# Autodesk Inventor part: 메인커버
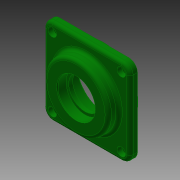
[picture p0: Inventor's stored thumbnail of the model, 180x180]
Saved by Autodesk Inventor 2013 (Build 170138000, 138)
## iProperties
Created: 2018-09
Part Number: 메인커버
Material: 알루미늄 6061
Document SubType Name: Modeling
Designer: mduedu
Density: 2.71 g/cm^3
Mass: 178.493 g
Surface Area: 197.445 cm^2
Volume: 65.8646 cm^3
Author: mduedu
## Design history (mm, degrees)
sketch "스케치1"
  geometry: L1 (-40, -40)-(40, -40); L2 (40, -40)-(40, 40); L3 (40, 40)-(-40, 40); L4 (-40, 40)-(-40, -40); L5 (-40, -40)-(40, 40); L6 (40, -40)-(-40, 40); 1 further point
  constraints: 12 end point, 2 midpoint, 2 parallel, 1 horizontal, 1 perpendicular
  dimensions: "d0" = 80 distance of L3.end L2.end; "d1" = 80 distance of L2.end L1.end
extrude "돌출1" new body sketch "스케치1" distance "d2" = 7; taper "d3" = 0 deg
sketch "스케치2"
  geometry: C1 r 30 at (0, 0); 1 further point
  constraints: 1 centre point, 1 coincident
  dimensions: "d4" = 60 diameter of C1
extrude "돌출2" join sketch "스케치2" distance "d5" = 10; taper "d6" = 0 deg
sketch "스케치3"
  geometry: C1 r 32.5 at (0, 0); 1 further point
  constraints: 1 centre point, 1 coincident
  dimensions: "d7" = 65 diameter of C1
extrude "돌출3" join sketch "스케치3" distance "d8" = 9; taper "d9" = 0 deg
sketch "스케치4"
  geometry: L1 (-32.5, -9)-(32.5, -9) reference; L2 (30, 17)-(-30, 17) reference; L3 (0, 17)-(0, -9); L4 (0, -9)-(23.5, -9); L5 (23.5, -9)-(23.5, 5); L6 (23.5, 5)-(0, 5); L7 (0, 5)-(0, -9); L8 (0, 5)-(15, 5); L9 (15, 5)-(15, 8.7); L10 (15, 8.7)-(0, 8.7); L11 (0, 8.7)-(0, 5); L12 (0, 8.7)-(17.5, 8.7); L13 (17.5, 8.7)-(17.5, 17); L14 (17.5, 17)-(0, 17); L15 (0, 17)-(0, 8.7); 1 further point
  constraints: 26 end point, 6 parallel, 3 horizontal, 3 perpendicular, 2 midpoint, 1 point on line
  dimensions: "d10" = 14 distance of L4.end L5.end; "d12" = 8.3 distance of L12.end L13.end; "d13" = 35 diameter of L13 L3; "d14" = 30 diameter of L9 L3; "d15" = 47 diameter of L5 L3
revolve "회전1" sketch "스케치4" stored, may be unused: angle "d16" = 90 deg
fillet "모깎기1" dims "d17" = 8
fillet "모깎기2" dims "d18" = 3
fillet "모깎기3" dims "d19" = 3
chamfer "모따기1" distance "d20" = 0.8; stored, may be unused: second distance "d21" = 2, angle "d22" = 30 deg
chamfer "모따기2" distance "d23" = 1; stored, may be unused: second distance "d24" = 2, angle "d25" = 30 deg
fillet "모깎기4" dims "d26" = 0.3
sketch "스케치5"
  geometry: A1 r 8 centre (-32, 32) between (-32, 40) and (-40, 32) reference; A2 r 8 centre (-32, -32) between (-40, -32) and (-32, -40) reference; A3 r 8 centre (32, -32) between (32, -40) and (40, -32) reference; A4 r 8 centre (32, 32) between (40, 32) and (32, 40) reference; 5 further points
  constraints: 4 coincident
hole "구멍1" sketch "스케치5" at (-32, 32), (32, 32), (32, -32), (-32, -32) diameter "d27" = 4.5; stored, may be unused: countersink angle "d31" = 90 deg, drill point angle "d33" = 118 deg; dims "d28" = 6, "d29" = 8, "d30" = 4.4, "d32" = 8
fillet "모깎기5" dims "d34" = 0.5
node "솔리드1"
